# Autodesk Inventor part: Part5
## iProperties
Created: 2002-01
Part Number: Part5
Document SubType Name: Modeling
Designer: ***
Control State: 0
Master: False
Checked Out: False
Shininess: 77.0
Angle Display Precision: 2
Document Length Units: 11269
Document Angle Units: 11279
Document Time Units: 11290
Document Mass Units: 11283
Document Length Units Precision: 3
Document Angle Units Precision: 2
Density: 0.0
Volumn: 0.0
Area: 0.0
PropertySet Name: Model Information
Author: ***
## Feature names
1. Extrusion1
2. Extrusion2
